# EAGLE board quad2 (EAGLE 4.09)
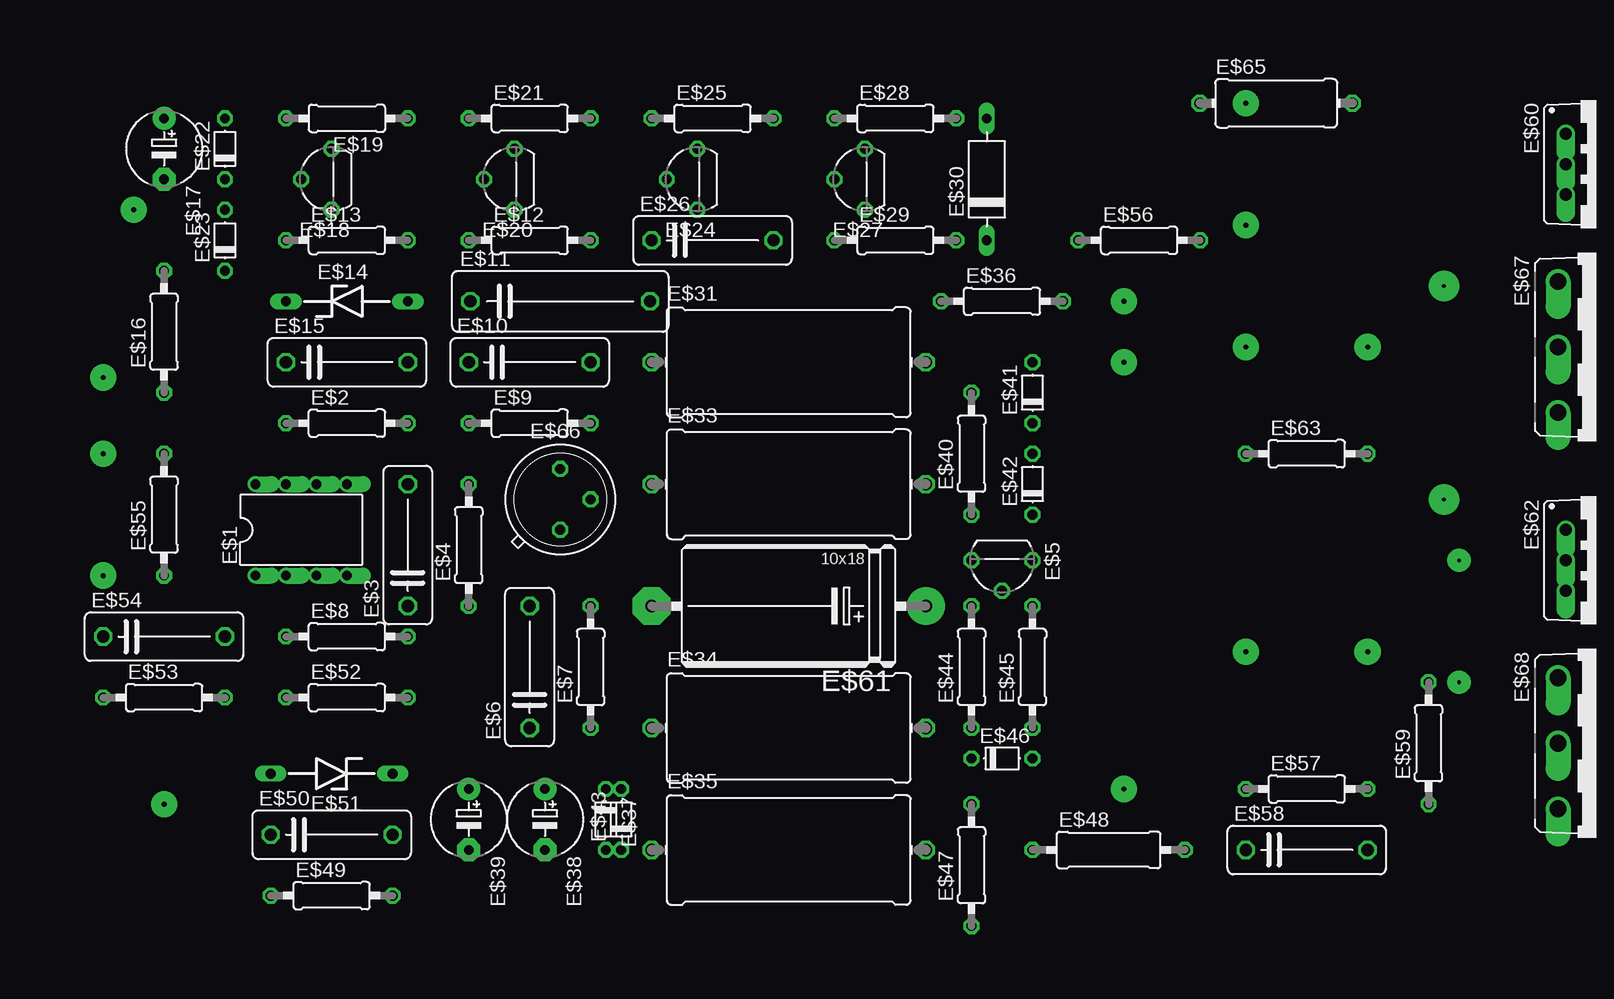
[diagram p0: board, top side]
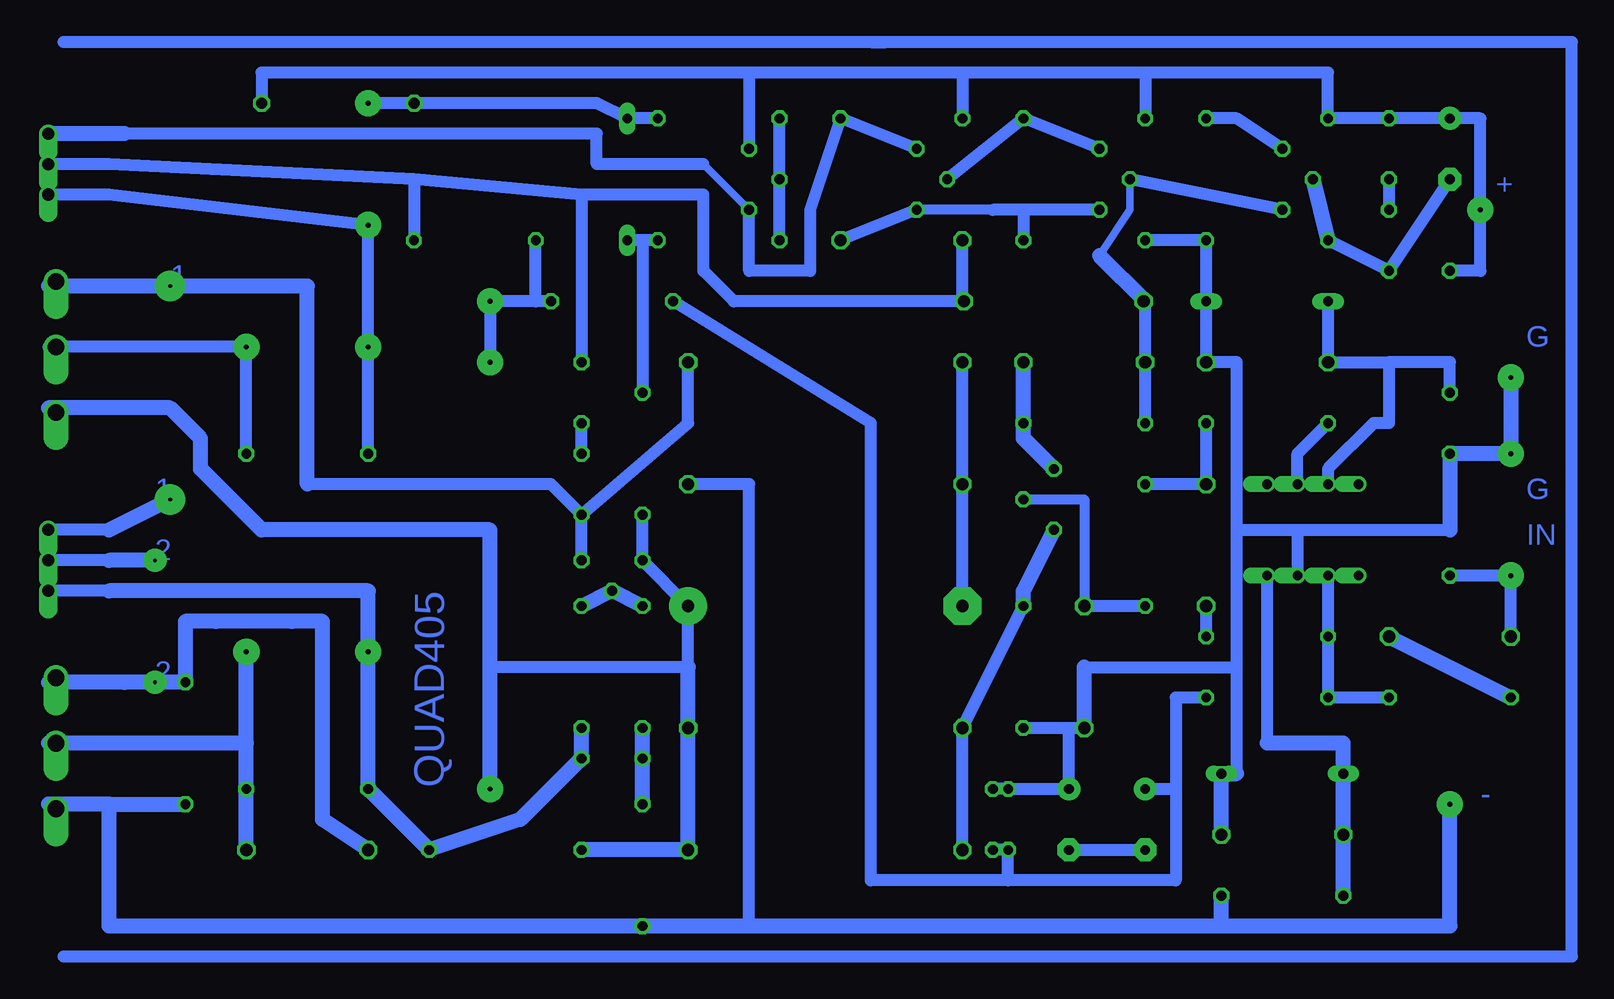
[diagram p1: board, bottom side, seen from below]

No outline drawn. Coordinates in mm, seen from the top.
Copper layers used: Bottom

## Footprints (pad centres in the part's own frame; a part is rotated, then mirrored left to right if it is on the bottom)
DIL-08 = drill 0.813 offset: 1 -3.81,-3.81; 2 -1.27,-3.81; 3 1.27,-3.81; 4 3.81,-3.81; 5 3.81,3.81; 6 1.27,3.81; 7 -1.27,3.81; 8 -3.81,3.81
0207/10 = drill 0.813 octagon: 1 -5.08,0; 2 5.08,0
C102-043X133 = drill 1.016 octagon: 1 -5.08,0; 2 5.08,0
TO92L = drill 0.813 octagon: 1 0,-2.54; 2 2.54,0; 3 0,2.54
C150-054X183 = drill 1.016 octagon: 1 -7.493,0; 2 7.493,0
ZDIO-10 = drill 0.813 long: A 5.08,0; C -5.08,0
E5-6 = drill 0.813 pad 1.905 round: + -2.54,0 | drill 0.813 pad 1.905 octagon: - 2.54,0
D-5 = drill 0.813 octagon: A 2.54,0; C -2.54,0
D-10 = drill 0.813 long: A 5.08,0; C -5.08,0
0922/22 = drill 1.016 octagon: 1 -11.43,0; 2 11.43,0
0309/12 = drill 0.813 octagon: 1 -6.35,0; 2 6.35,0
TO220V = drill 1.016 offset: 1 -2.54,-2.54; 2 0,-2.54; 3 2.54,-2.54
E22-10 = drill 1.016 pad 3.15 round: + -11.43,0 | drill 1.016 pad 3.15 octagon: - 11.43,0
0411/12 = drill 0.914 octagon: 1 -6.35,0; 2 6.35,0
TO5 = drill 0.813 octagon: 1 0,-2.54; 2 2.54,0; 3 0,2.54
TOP3V = drill 1.397 offset: B -5.461,-3.175; C 0,-3.175; E 5.461,-3.175

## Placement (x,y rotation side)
E$1  OPA604  [DIL-08]  64.77,39.37 0 top
E$2  1k  [0207/10]  68.58,48.26 0 top
E$3  47n  [C102-043X133]  73.66,38.1 90 top
E$4  3k  [0207/10]  78.74,38.1 90 top
E$5  BC212  [TO92L]  123.19,36.83 270 top
E$6  1nF  [C102-043X133]  83.82,27.94 90 top
E$7  180  [0207/10]  88.9,27.94 90 top
E$8  330k  [0207/10]  68.58,30.48 0 top
E$9  3,3k  [0207/10]  83.82,48.26 0 top
E$10  330p  [C102-043X133]  83.82,53.34 0 top
E$11  120pF  [C150-054X183]  86.36,58.42 0 top
E$12  1,2k  [0207/10]  83.82,63.5 0 top
E$13  22k  [0207/10]  68.58,63.5 0 top
E$14  ZPD15  [ZDIO-10]  68.58,58.42 0 top
E$15  5uF Ta  [C102-043X133]  68.58,53.34 0 top
E$16  3,3k  [0207/10]  53.34,55.88 90 top
E$17  [E5-6]  53.34,71.12 270 top
E$18  BC212  [TO92L]  67.31,68.58 180 top
E$19  100  [0207/10]  68.58,73.66 180 top
E$20  BC212  [TO92L]  82.55,68.58 180 top
E$21  3,3k  [0207/10]  83.82,73.66 0 top
E$22  1N4148  [D-5]  58.42,71.12 90 top
E$23  1N4148  [D-5]  58.42,63.5 90 top
E$24  BC212  [TO92L]  97.79,68.58 180 top
E$25  270  [0207/10]  99.06,73.66 0 top
E$26  330p  [C102-043X133]  99.06,63.5 0 top
E$27  BC212  [TO92L]  111.76,68.58 180 top
E$28  75  [0207/10]  114.3,73.66 0 top
E$29  22  [0207/10]  114.3,63.5 0 top
E$30  [D-10]  121.92,68.58 90 top
E$31  560ohm/2W  [0922/22]  105.41,53.34 0 top
E$33  560ohm/2W  [0922/22]  105.41,43.18 0 top
E$34  1k/2W  [0922/22]  105.41,22.86 0 top
E$35  1k/2W  [0922/22]  105.41,12.7 0 top
E$36  4,7k  [0207/10]  123.19,58.42 0 top
E$37  1N4148  [D-5]  90.17,15.24 270 top
E$38  220u  [E5-6]  85.09,15.24 270 top
E$39  220u  [E5-6]  78.74,15.24 270 top
E$40  15k  [0207/10]  120.65,45.72 90 top
E$41  [D-5]  125.73,50.8 90 top
E$42  [D-5]  125.73,43.18 90 top
E$43  [D-5]  91.44,15.24 90 top
E$44  22  [0207/10]  120.65,27.94 90 top
E$45  75  [0207/10]  125.73,27.94 90 top
E$46  [D-5]  123.19,20.32 0 top
E$47  15k  [0207/10]  120.65,11.43 90 top
E$48  0,091  [0309/12]  132.08,12.7 0 top
E$49  3,3k  [0207/10]  67.31,8.89 0 top
E$50  5uF Ta +  [C102-043X133]  67.31,13.97 0 top
E$51  [ZDIO-10]  67.31,19.05 180 top
E$52  22k  [0207/10]  68.58,25.4 0 top
E$53  22k  [0207/10]  53.34,25.4 0 top
E$54  1uF  [C102-043X133]  53.34,30.48 0 top
E$55  220k  [0207/10]  53.34,40.64 90 top
E$56  47  [0207/10]  134.62,63.5 0 top
E$57  22  [0207/10]  148.59,17.78 0 top
E$58  3,3nF  [C102-043X133]  148.59,12.7 0 top
E$59  22  [0207/10]  158.75,21.59 90 top
E$60  [TO220V]  172.72,69.85 270 top
E$61  47uF/63V Ta  [E22-10]  105.41,33.02 180 top
E$62  [TO220V]  172.72,36.83 270 top
E$63  22  [0207/10]  148.59,45.72 0 top
E$65  0,091  [0411/12]  146.05,74.93 0 top
E$66  2N2219A, BFY34  [TO5]  86.36,41.91 0 top
E$67  [TOP3V]  172.72,54.61 270 top
E$68  [TOP3V]  172.72,21.59 270 top

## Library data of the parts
E$1 = ic-package
E$2-E$4 E$6-E$13 E$15-E$17 E$19 E$21 E$25 E$26 E$28 E$29 E$31 E$33-E$36 E$38-E$40 E$44 E$45 E$47-E$50 E$52-E$59 E$61 E$63 E$65 = rcl
E$5 E$18 E$20 E$24 E$27 E$60 E$62 E$66 = transistor-pnp
E$14 E$22 E$23 E$30 E$37 E$41-E$43 E$46 E$51 = diode
E$67 E$68 = transistor-npn

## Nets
S$1: E$1.6 E$2.1
S$2: E$2.2 E$3.2 E$4.2
S$3: E$19.1
S$4: E$1.4 E$49.1 E$50.1 E$51.A
S$5: E$31.2 E$42.C
S$6: E$1.3 E$6.1 E$7.1 E$12.1 E$13.2 E$14.A E$15.2 E$37.C E$38.+ E$43.A E$50.2 E$51.C E$55.2
S$7: E$1.2 E$8.1 E$52.1 E$53.2
S$8: E$3.1 E$8.2
S$9: E$9.2 E$10.2
S$10: E$9.1 E$10.1
S$11: E$60.3 E$63.1
S$13: E$1.7 E$14.C E$15.1 E$16.1
S$14: E$21.2
S$15: E$31.1
S$16: E$22.C E$23.A
S$17: E$16.2 E$17.+ E$19.2 E$21.1 E$22.A E$25.1 E$65.2
S$18: E$13.1 E$17.- E$23.C
S$19: E$63.2
S$20: E$7.2 E$34.1 E$35.1
S$21: E$4.1 E$6.2 E$66.2
S$22: E$57.2 E$58.2
S$23: E$28.1 E$29.1
S$25: E$29.2 E$30.C E$40.2
S$26: E$25.2 E$60.1
S$27: E$38.- E$39.-
S$28: E$45.1 E$46.A E$48.2 E$57.1 E$62.3
S$29: E$41.C E$42.A
S$30: E$12.2 E$26.2
S$32: E$44.2 E$45.2
S$34: E$44.1 E$47.2
S$35: E$35.2 E$40.1 E$48.1
S$36: E$33.2 E$47.1 E$49.2 E$59.1
S$37: E$62.1
S$38: E$62.2
S$39: E$36.1 E$37.A E$39.+ E$43.C E$52.2
S$41: E$53.1 E$54.2
S$42: E$54.1
S$43: E$26.1 E$41.A E$56.2 E$60.2
S$46: E$28.2 E$30.A E$65.1
S$47: E$58.1 E$59.2
S$49: E$36.2 E$56.1

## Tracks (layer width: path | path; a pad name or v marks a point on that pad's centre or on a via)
S$1
  Bottom 1.016: E$1.6 66.04,45.72 E$2.1
S$2
  Bottom 1.016: E$2.2 E$3.2 E$4.2
S$3
  Bottom 1.016: E$19.1 71.12,73.66 67.31,71.12
S$4
  Bottom 1.016: E$1.4 68.58,21.59 | E$49.1 E$50.1 E$51.A 62.23,21.59
  Bottom 1.27: E$49.1 62.23,21.59 68.58,21.59
S$5  (via drill 0.3 pad 2.54)
  Bottom 1.016: v160.02,59.69 162.56,59.69 | E$31.2 116.84,48.26 E$42.C | 148.59,43.18 128.27,43.18 E$42.C | 125.73,36.83 E$42.C
  Bottom 1.27: 163.83,59.69 170.18,59.69 | 162.56,59.69 163.83,59.69 | 163.83,59.69 v160.02,59.69 148.59,59.69 148.59,43.18
S$6  (via drill 0.41 pad 2.18)
  Bottom 1.016: E$7.1 85.09,22.86 | 85.09,22.86 E$6.1 | 85.09,22.86 E$38.+ E$37.C E$43.A | E$50.2 E$51.C | 71.12,19.05 71.12,27.94 | 71.12,27.94 71.12,39.37 | 71.12,39.37 71.12,53.34 E$15.2 E$14.A E$13.2 E$12.1 | 71.12,39.37 66.04,39.37 | 66.04,39.37 E$1.3 | 66.04,39.37 53.34,39.37 | E$55.2 v48.26,45.72 v48.26,52.07 | 83.82,27.94 71.12,27.94
  Bottom 1.27: E$6.1 83.82,27.94 | E$50.2 E$51.C 71.12,19.05 | v48.26,52.07 v48.26,45.72 E$55.2 53.34,39.37
S$7
  Bottom 1.016: E$1.2 E$8.1 E$52.1 E$53.2
S$8
  Bottom 1.016: E$8.2 E$3.1
S$9
  Bottom 1.016: E$10.2 E$9.2 88.9,46.99
  Bottom 1.27: 86.36,44.45 88.9,46.99 E$10.2
S$10
  Bottom 0.61: 82.55,62.23 80.01,66.04 80.01,68.58
  Bottom 1.016: E$9.1 E$10.1 78.74,58.42 | 67.31,66.04 80.01,68.58
  Bottom 1.27: 78.74,58.42 82.55,62.23
S$11  (via drill 0.41 pad 2.18)
  Bottom 1.016: E$63.1 v143.51,54.61 v143.51,64.77 165.1,67.31 E$60.3
S$12
  Bottom 1.016: 163.83,49.53 165.1,49.53
S$13
  Bottom 1.016: E$16.1 53.34,53.34 58.42,53.34 | E$14.C E$15.1 58.42,53.34 | 58.42,53.34 58.42,48.26 59.69,48.26 63.5,44.45 E$1.7
S$14
  Bottom 1.016: 82.55,71.12 E$21.2 95.25,68.58
S$15
  Bottom 1.016: 93.98,33.02 E$31.1
S$16
  Bottom 1.016: E$22.C E$23.A
S$17  (via drill 0.41 pad 2.18)
  Bottom 1.016: 78.74,77.47 E$21.1 | 78.74,77.47 63.5,77.47 E$19.2 E$22.A E$17.+ 50.8,73.66 v50.8,66.04 50.8,60.96 E$16.2 | 78.74,77.47 93.98,77.47 | 93.98,77.47 E$25.1 | 93.98,77.47 111.76,77.47 | 111.76,77.47 111.76,71.12 | 111.76,77.47 152.4,77.47 E$65.2
S$18
  Bottom 1.016: E$17.- E$23.C E$13.1
  Bottom 1.27: 64.77,68.58 E$13.1
S$19  (via drill 0.41 pad 2.18)
  Bottom 1.016: 170.18,54.61 v153.67,54.61 E$63.2
S$20
  Bottom 1.016: E$35.1 E$34.1 E$7.2
  Bottom 1.27: E$7.2 88.9,34.29 86.36,39.37
S$21
  Bottom 0.61: E$6.2 83.82,36.83
  Bottom 0.813: E$66.2 83.82,41.91 E$6.2
  Bottom 1.016: E$4.1 E$6.2
S$22  (via drill 0.41 pad 2.18)
  Bottom 1.016: 153.67,21.59 E$57.2 E$58.2
  Bottom 1.27: 153.67,21.59 v153.67,29.21 | E$58.2 153.67,21.59 | 153.67,21.59 170.18,21.59
S$23
  Bottom 1.016: E$29.1 E$28.1
S$24
  Bottom 1.016: 101.6,80.01 100.33,80.01 | 101.6,80.01 168.91,80.01 | 168.91,3.81 43.18,3.81 43.18,80.01 101.6,80.01
S$25
  Bottom 1.016: E$29.2 120.65,63.5 | 120.65,63.5 E$30.C | 120.65,63.5 E$40.2
S$26
  Bottom 0.61: 111.76,66.04 115.57,69.85
  Bottom 1.016: 111.76,66.04 111.76,60.96 106.68,60.96 106.68,66.04 E$25.2 97.79,71.12 | 165.1,72.39 163.83,72.39 124.46,72.39 124.46,69.85 115.57,69.85
  Bottom 1.27: 163.83,72.39 E$60.1
S$27
  Bottom 1.016: E$38.- E$39.-
S$28  (via drill 0.41 pad 2.18)
  Bottom 1.016: E$48.2 E$57.1 v143.51,29.21 143.51,34.29 | E$46.A E$45.1 | 165.1,34.29 E$62.3
  Bottom 1.27: 165.1,34.29 143.51,34.29 E$57.1 E$48.2 130.81,15.24 E$46.A E$45.1
S$29
  Bottom 1.016: E$42.A E$41.C
S$30
  Bottom 0.813: 91.44,66.04 97.79,66.04
  Bottom 1.016: 97.79,66.04 E$26.2 | 88.9,66.04 91.44,66.04 | 88.9,66.04 E$12.2 | 82.55,66.04 88.9,66.04
S$32
  Bottom 1.27: E$44.2 123.19,34.29 E$45.2
S$34
  Bottom 1.016: E$47.2 E$44.1
  Bottom 1.27: E$47.2 E$44.1
S$35  (via drill 0.41 pad 2.18)
  Bottom 1.016: E$40.1 120.65,36.83 116.84,33.02 116.84,27.94 133.35,27.94 | 133.35,27.94 v133.35,17.78 | 133.35,27.94 133.35,39.37 | E$35.2 E$48.1
  Bottom 1.27: v133.35,17.78 133.35,39.37 152.4,39.37 157.48,44.45 157.48,46.99 160.02,49.53 170.18,49.53 | E$48.1 E$35.2 116.84,27.94
S$36  (via drill 0.41 pad 2.18)
  Bottom 1.016: 111.76,6.35 E$47.1 165.1,6.35 | 111.76,6.35 111.76,43.18 E$33.2 | 72.39,6.35 111.76,6.35
  Bottom 1.27: 165.1,16.51 E$59.1 | 165.1,16.51 165.1,6.35 72.39,6.35 | 72.39,6.35 53.34,6.35 v53.34,16.51 | 72.39,6.35 E$49.2 | 165.1,16.51 170.18,16.51
S$37  (via drill 0.3 pad 2.54)
  Bottom 1.016: 165.1,39.37 E$62.1
  Bottom 1.27: v160.02,41.91 165.1,39.37
S$38  (via drill 0.3 pad 1.93)
  Bottom 1.016: 165.1,36.83 E$62.2
  Bottom 1.27: v161.29,36.83 165.1,36.83
S$39
  Bottom 1.016: E$52.2 76.2,25.4 76.2,17.78 | E$39.+ 76.2,17.78 | 76.2,17.78 76.2,10.16 90.17,10.16 | 90.17,10.16 E$37.A E$43.C | 90.17,10.16 101.6,10.16 101.6,48.26 E$36.1
S$41
  Bottom 1.016: E$53.1 E$54.2
  Bottom 1.27: E$53.1 E$54.2
S$42  (via drill 0.41 pad 2.18)
  Bottom 1.016: 53.34,35.56 v48.26,35.56 E$54.1
S$43
  Bottom 1.016: 139.7,68.58 165.1,69.85 E$60.2 | 139.7,68.58 E$56.2 | 125.73,67.31 E$41.A | 125.73,67.31 139.7,68.58 | 125.73,67.31 115.57,67.31 115.57,60.96 113.03,58.42 93.98,58.42 E$26.1
S$46  (via drill 0.41 pad 2.18)
  Bottom 1.016: E$28.2 E$30.A 124.46,74.93 E$65.1 v143.51,74.93
S$47  (via drill 0.3 pad 1.93)
  Bottom 0.61: 151.13,31.75 156.21,31.75
  Bottom 1.016: 163.83,26.67 165.1,26.67 | 149.86,31.75 151.13,31.75
  Bottom 1.27: E$58.1 147.32,15.24 147.32,31.75 149.86,31.75 156.21,31.75 158.75,31.75 E$59.2 v161.29,26.67 163.83,26.67 170.18,26.67
S$49  (via drill 0.41 pad 2.18)
  Bottom 1.016: E$36.2 129.54,58.42 | 129.54,58.42 v133.35,58.42 v133.35,53.34 | 129.54,58.42 E$56.1

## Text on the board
Bottom: + | 1 | G | G | 1 | IN | 2 | QUAD405 | 2 | -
